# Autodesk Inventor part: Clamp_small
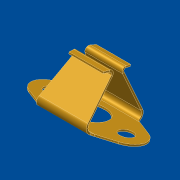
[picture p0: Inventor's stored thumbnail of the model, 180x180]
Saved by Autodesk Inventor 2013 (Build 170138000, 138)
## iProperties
Shininess: 25.0
Length Units: 11269
Angle Units: 11279
Time Units: 11290
Mass Units: 11283
Length Display Precision: 3
Angle Display Precision: 2
Created: 2001-04
Part Number: Clamp_small
Material: Standard
Document SubType Name: Modellieren
Designer: dl
Density: 1 g/cm^3
Sheet Metal Rule: Norm
Density: 0.0
Volumn: 0.0
Area: 0.0
PropertySet Name: Model Information
Control State: 0
Master: False
Checked Out: False
Author: dl
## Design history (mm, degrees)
body "Solid1"
node "Fläche1"
sketch "Sketch2"
  geometry: L1 (0, 0)-(-2, 13.75) reference; L2 (10, 13.75)-(8, 0) reference; L3 (8, 39)-(10, 25.25) reference; L4 (0, 39)-(8, 39) reference; L5 (-2, 25.25)-(0, 39) reference; L6 (-1.855, 26.25)-(9.855, 26.25); L7 (-1.855, 12.75)-(9.855, 12.75)
  constraints: 4 end point, 4 point on line, 2 parallel
  dimensions: "d15" = 1 distance from line of L5.start L6; "d16" = 1 distance from line of L1.end L7 (= d15)
feature "Freie Lasche1" dims "d18" = 125 deg, "d19" = 1, "d44" = 0.4 (= BreiteBiegungsfreistellung), "d45" = 0.2 (= TiefeBiegungsfreistellung), "d46" = 0.8 (= MinimalRest), "Objekthöhe" = 0.4, "AbstandVerbindung" = 0.01
feature "Freie Lasche2" dims "d20" = 125 deg, "d21" = 1, "d47" = 0.4 (= BreiteBiegungsfreistellung), "d48" = 0.2 (= TiefeBiegungsfreistellung), "d49" = 0.8 (= MinimalRest), "Objekthöhe" = 0.4
feature "Freie Lasche3" dims "d23" = 130 deg, "d24" = 0.4 (= Biegeradius), "d50" = 0.4 (= BreiteBiegungsfreistellung), "d51" = 0.2 (= TiefeBiegungsfreistellung), "d52" = 0.8 (= MinimalRest), "Objekthöhe" = 0.4
feature "Freie Lasche4" dims "d26" = 130 deg, "d27" = 0.4 (= Biegeradius), "d53" = 0.4 (= BreiteBiegungsfreistellung), "d54" = 0.2 (= TiefeBiegungsfreistellung), "d55" = 0.8 (= MinimalRest), "Objekthöhe" = 0.4
sketch "Sketch5"
  geometry: A1 r 4 centre (-2.159, 5.467) between (-3.885, 9.075) and (-3.885, 1.859) reference; A2 r 4 centre (15.341, 5.467) between (17.067, 1.859) and (17.067, 9.075) reference; 2 further points
  constraints: 2 coincident
hole "Hole1" sketch "Sketch5" diameter "d28" = 3.2; stored, may be unused: countersink angle "d32" = 60 deg, drill point angle "d34" = 118 deg; dims "d29" = 6, "d30" = 4, "d31" = 2, "d33" = 1
sketch "Sketch6"
  geometry: C1 r 1.6 at (-2.159, 5.467) reference; 1 further point
  dimensions: "d35" = 8.75 distance of point (6.591, 5.467) C1.centre; "d36" = 0 vertical distance of C1.centre point (6.591, 5.467)
hole "Hole2" sketch "Sketch6" diameter "d37" = 7.8; stored, may be unused: countersink angle "d41" = 60 deg, drill point angle "d43" = 118 deg; dims "d38" = 6, "d39" = 4, "d40" = 2, "d42" = 1
sketch "Sketch1"
  geometry: L1 (10.179, 12.278)-(14.656, 14.42); L2 (10.179, 5.062)-(14.656, 2.92); L3 (31.132, 12.278)-(26.656, 14.42); L4 (31.132, 5.062)-(26.656, 2.92); L5 (14.656, 14.42)-(16.656, 28.17); L6 (16.656, 28.17)-(24.656, 28.17); L7 (24.656, 28.17)-(26.656, 14.42); L8 (14.656, 2.92)-(16.656, -10.83); L9 (16.656, -10.83)-(24.656, -10.83); L10 (24.656, -10.83)-(26.656, 2.92); A1 r 4 centre (11.906, 8.67) between (10.179, 12.278) and (10.179, 5.062); A2 r 4 centre (29.406, 8.67) between (31.132, 5.062) and (31.132, 12.278)
  constraints: 20 end point, 5 equal length, 4 point on circle, 4 tangent, 2 centre point, 2 horizontal, 2 parallel, 1 equal radius
  dimensions: "d0" = 4 radius of A2; "d1" = 17.5 distance of A2.centre A1.centre; "d2" = 12 distance of L3.end L1.end; "d3" = 12 distance of L4.end L2.end (= d2); "d4" = 8 distance of L5.end L6.end; "d5" = 8 distance of L8.end L9.end (derived); "d6" = 11.5 distance of L2.end L1.end; "d7" = 4.75 horizontal distance of L8.end A1.centre (= -0.5 x d5 + 0.5 x d1); "d8" = 4.75 horizontal distance of L5.end A1.centre (= d7); "d12" = 39 distance between parallel lines of L9 L6; "d13" = 19.5 distance from line of A1.centre L6 (= 0.5 x d12)
feature "Platte1" dims "Objekthöhe" = 0.4
sketch "Sketch3"
  geometry: L1 (0, 0)-(-1.668, 11.467) reference; L2 (8, 0)-(0, 0) reference; L3 (9.668, 11.467)-(8, 0) reference; L4 (-0.291, 2)-(8.291, 2)
  constraints: 2 end point, 2 point on line, 1 parallel
  dimensions: "d22" = 2 distance between parallel lines of L2 L4
sketch "Sketch4"
  geometry: L1 (8, 0)-(9.668, -11.467) reference; L2 (0, 0)-(8, 0) reference; L3 (-1.668, -11.467)-(0, 0) reference; L4 (-0.291, -2)-(8.291, -2)
  constraints: 2 end point, 2 point on line, 1 parallel
  dimensions: "d25" = 2 distance from line of L1.start L4
other parameters: "d9" = 21.81081, "d10" = 13.40976, "d11" = 17.99317, "Biegeradius" = 0.4 (= Objekthöhe), "BreiteBiegungsfreistellung" = 0.4 (= Objekthöhe), "TiefeBiegungsfreistellung" = 0.2 (= 0.5 x Objekthöhe), "GrößeEckenfreistellung" = 1.6 (= 4 x Objekthöhe), "MinimalRest" = 0.8 (= 2 x Objekthöhe), "d14" = 0.4 (= Biegeradius), "d17" = 0 (derived), "Übergangsradius" = 0.4 (= Biegeradius), "JacobiRadiusSize" = 0.4 (= Objekthöhe), "GapSize" = 0.4 (= Objekthöhe)
